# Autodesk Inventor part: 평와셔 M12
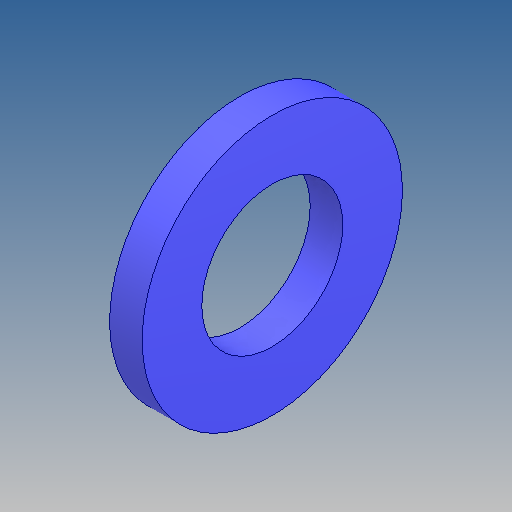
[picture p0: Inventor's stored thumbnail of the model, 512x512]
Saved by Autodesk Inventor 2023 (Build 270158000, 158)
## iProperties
Created: 2025-03
Part Number: 평와셔 M12
Material: 스테인리스강
Description: 평면 와셔
Document SubType Name: Modeling
Designer: Admin
Density: 8.08 g/cm^3
Appearance: 기본값
Author: jhkim
Sending System: Autodesk Inventor 2025
Preprocessor: ST-DEVELOPER v20
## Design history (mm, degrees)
node "평와셔 M121"
node "솔리드1"
body "Solid1"
